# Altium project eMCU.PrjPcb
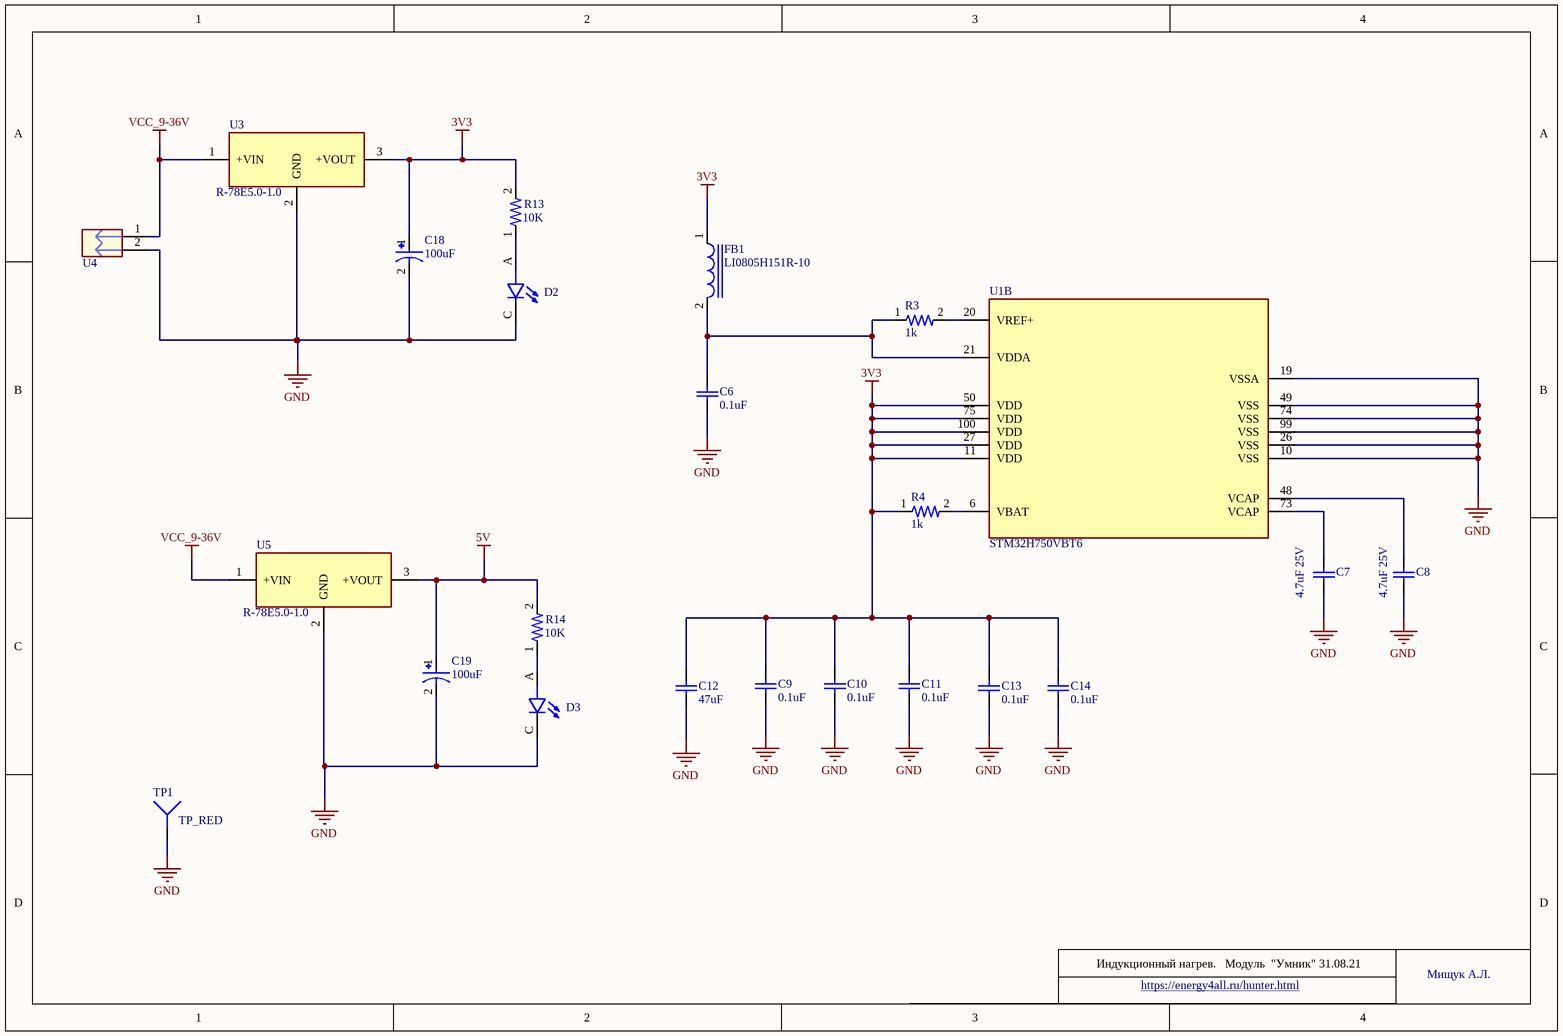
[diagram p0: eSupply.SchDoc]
6 sheets, 104 parts. Net scope: flat (ports and power ports of the same name join across sheets).
Board file: eMCU.PcbDoc
Sheets:
  eSupply.SchDoc
  eMCU.SchDoc
  eUSB.SchDoc
  eWiFi.SchDoc
  eConnect.SchDoc
  Can.SchDoc

## Sheet eSupply.SchDoc
size A4; SheetNumber: 1; SheetTotal: 7

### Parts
(Parts that share a designator on the sheet are numbered #1, #2 ... from top to bottom, then left to right.)
C6  0.1uF  [CAP_0603]
C7  4.7uF 25V  [CAP_0603]
C8  4.7uF 25V  [CAP_0603]
C9  0.1uF  [CAP_0603]
C10  0.1uF  [CAP_0603]
C11  0.1uF  [CAP_0603]
C12  47uF  [CAP_1210]
C13  0.1uF  [CAP_0603]
C14  0.1uF  [CAP_0603]
C18  100uF  [CAP_TYPE_D]
C19  100uF  [CAP_TYPE_D]
D2#1  led_0603  [led_0603]  (value not drawn)
D3  led_0603  [led_0603]  (value not drawn)
FB1  LI0805H151R-10  [LI0805H151R-10]
R3  1k  [RESC1608X50N]
R4  1k  [RESC1608X50N]
R13  10K  [RESC1608X50N]
R14  10K  [RESC1608X50N]
TP1  TP_RED  [TP_RED]
U1  STM32H750VBT6  [STM32H750VBT6]  (part B of 5)
U3  R-78E5.0-1.0  [R-78E5.0-1.0]
U4  DG129-5.0-02P  [DG129-5.0-02P]  (value not drawn)
U5  R-78E5.0-1.0  [R-78E5.0-1.0]

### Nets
3V3: C9.2 C10.2 C11.2 C12.2 C13.2 C14.2 C18.1 FB1.1 R4.1 R13.2 U1.11(VDD) U1.27(VDD) U1.50(VDD) U1.75(VDD) U1.100(VDD) U3.3(+VOUT)
5V: C19.1 R14.2 U5.3(+VOUT)
GND: C6.1 C7.1 C8.1 C9.1 C10.1 C11.1 C12.1 C13.1 C14.1 C18.2 C19.2 D2#1.C D3.C TP1.1 U1.10(VSS) U1.19(VSSA) U1.26(VSS) U1.49(VSS) U1.74(VSS) U1.99(VSS) U3.2(GND) U4.2 U5.2(GND)
VCC_9-36V: U3.1(+VIN) U4.1 U5.1(+VIN)
NetC6_2: C6.2 FB1.2 R3.1 U1.21(VDDA)
NetC7_2: C7.2 U1.73(VCAP)
NetC8_2: C8.2 U1.48(VCAP)
NetD2#1_A: D2#1.A R13.1
NetD3_A: D3.A R14.1
NetR3_2: R3.2 U1.20(VREF+)
NetR4_2: R4.2 U1.6(VBAT)

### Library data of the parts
C6-C11 C13 C14 = CAP_0603
C12 = CAP_1210
C18 C19 = CAP_TYPE_D: MP: 25TQC15MV
D2#1 D3 = led_0603: LED Indication - Discrete 3.1V 0603 _1608 Metric_; MP: LTW-C191TLA; MF: Lite-On
FB1 = LI0805H151R-10: 150 Ohms @ 100MHz 1 Power, Signal Line Ferrite Bead 0805 (2012 Metric) 800mA 150mOhm; MF: Laird-Signal Integrity
R3 R4 R13 R14 = RES_0603: 1% 0.1W; MP: 1-2176071-4
TP1 = TP_RED: RF EMI Absorbing Sheet - Polyurethane Foam 24.000 (609.60mm) X 24.000 (609.60mm) X 0.252 (6.40mm); MF: Aeroflex; MP: 5010
U1 = STM32H750VBT6: ARM Cortex-M7 STM32H7 Microcontroller IC 32-Bit 480MHz 128KB _128K x 8_ FLASH 100-LQFP _14x14_; MF: STMicroelectronics
U3 U5 = R-78E5.0-1.0: 1A DC/DC-Converter SIP3; MF: Recom Power
U4 = DG129-5.0-02P: DG129-5.0-02P-14-00A(H)

## Sheet eMCU.SchDoc
size A4; SheetNumber: 2; SheetTotal: 7
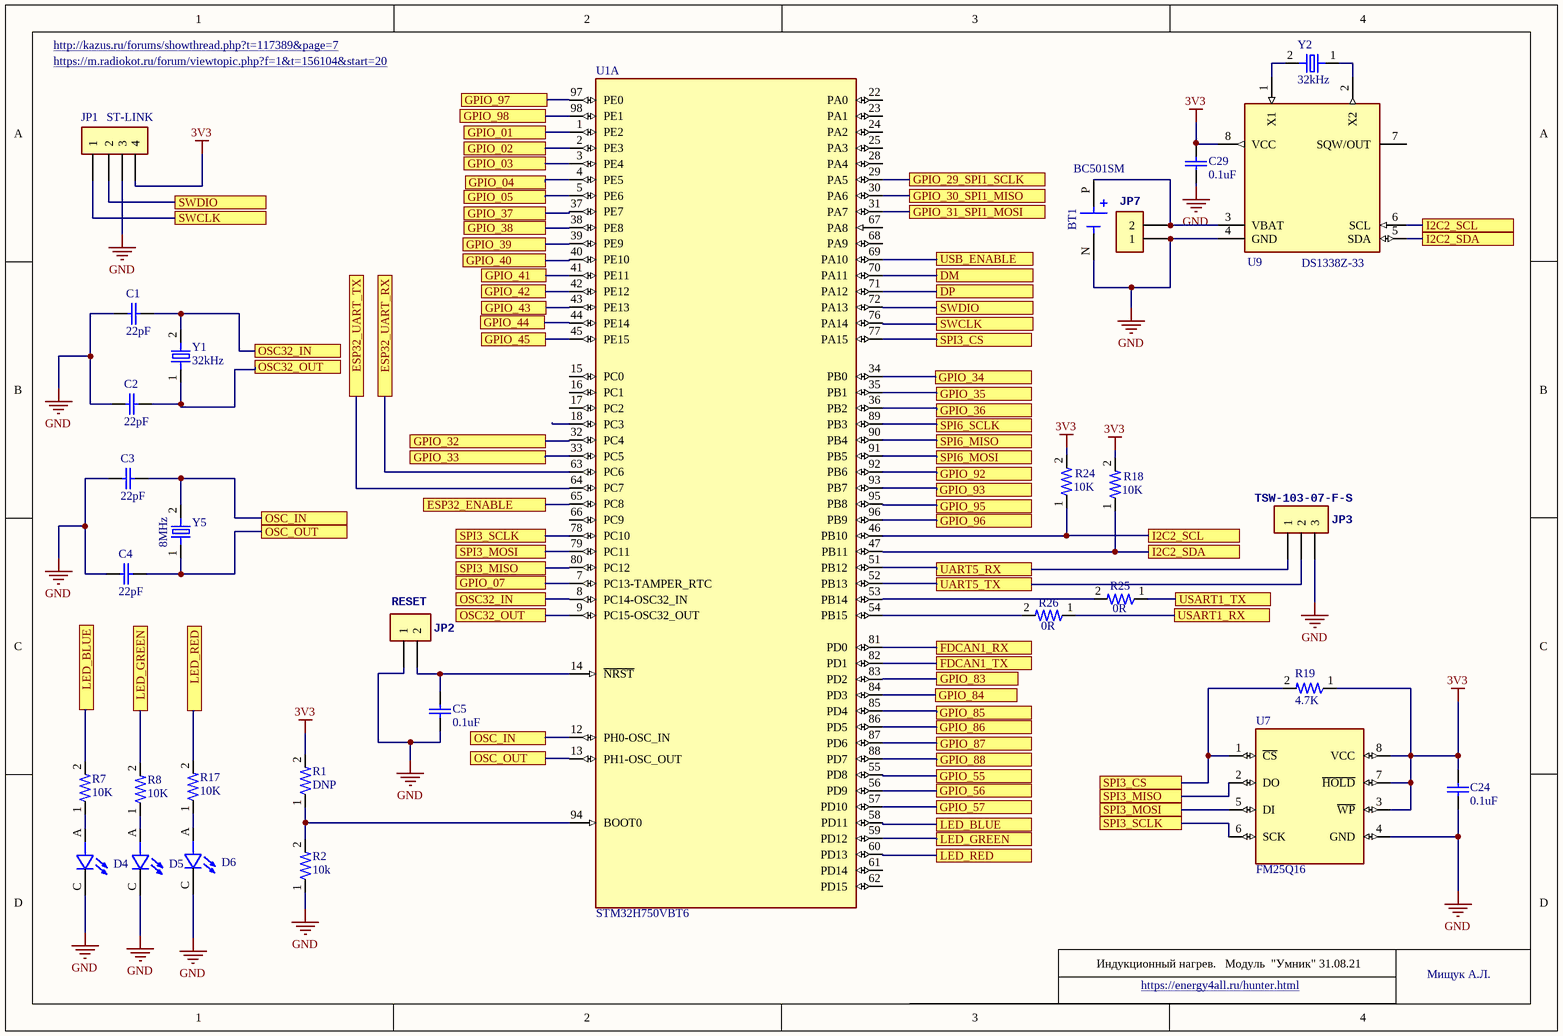
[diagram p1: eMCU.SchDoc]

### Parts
BT1  BC501SM  [BAT_BC501SM]
C1  22pF  [CAP_0603]
C2  22pF  [CAP_0603]
C3  22pF  [CAP_0603]
C4  22pF  [CAP_0603]
C5  0.1uF  [CAP_0603]
C24  0.1uF  [CAP_0603]
C29  0.1uF  [CAP_0603]
D4  led_0603  [led_0603]  (value not drawn)
D5  led_0603  [led_0603]  (value not drawn)
D6  led_0603  [led_0603]  (value not drawn)
JP1  ST-LINK  [TSW-104-07-F-S]
JP2  RESET  [TSW-102-07-F-S]
JP3  TSW-103-07-F-S  [TSW-103-07-F-S]
JP7  TSW-102-07-F-S  [TSW-102-07-F-S]  (value not drawn)
R1  DNP  [RESC1608X50N]
R2  10k  [RESC1608X50N]
R7  10K  [RESC1608X50N]
R8  10K  [RESC1608X50N]
R17  10K  [RESC1608X50N]
R18  10K  [RESC1608X50N]
R19  4.7K  [RESC1608X50N]
R24  10K  [RESC1608X50N]
R25  0R  [RESC1608X50N]
R26  0R  [RESC1608X50N]
U1  STM32H750VBT6  [STM32H750VBT6]  (part A of 5)
U7  FM25Q16  [FM25Q16]
U9  DS1338Z-33  [DS1338Z-33]
Y1  32kHz  [NX3215SA]
Y2  32kHz  [NX3215SA]
Y5  8MHz  [NX3225GD]

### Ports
DM, DP, ESP32_ENABLE, ESP32_UART_RX, ESP32_UART_TX, FDCAN1_RX, FDCAN1_TX, GPIO_01, GPIO_02, GPIO_03, GPIO_04, GPIO_05, GPIO_07, GPIO_29_SPI1_SCLK, GPIO_30_SPI1_MISO, GPIO_31_SPI1_MOSI, GPIO_32, GPIO_33, GPIO_34, GPIO_35, GPIO_36, GPIO_37, GPIO_38, GPIO_39, GPIO_40, GPIO_41, GPIO_42, GPIO_43, GPIO_44, GPIO_45, GPIO_55, GPIO_56, GPIO_57, GPIO_83, GPIO_84, GPIO_85, GPIO_86, GPIO_87, GPIO_88, GPIO_92, GPIO_93, GPIO_95, GPIO_96, GPIO_97, GPIO_98, I2C2_SCL, I2C2_SDA, LED_BLUE, LED_GREEN, LED_RED, OSC32_IN, OSC32_OUT, OSC_IN, OSC_OUT, SPI3_CS, SPI3_MISO, SPI3_MOSI, SPI3_SCLK, SPI6_MISO, SPI6_MOSI, SPI6_SCLK, SWCLK, SWDIO, UART5_RX, UART5_TX, USART1_RX, USART1_TX, USB_ENABLE

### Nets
3V3: C24.2 C29.2 JP1.4 R1.2 R18.2 R19.1 R24.2 U7.3(~{WP}) U7.7(~{HOLD}) U7.8(VCC) U9.8(VCC)
GND: BT1.N(NEG) C1.1 C2.1 C3.1 C4.1 C5.1 C24.1 C29.1 D4.C D5.C D6.C JP1.3 JP2.1 JP3.3 JP7.1 R2.1 U7.4(GND) U9.4(GND)
NetBT1_P: BT1.P(POS) JP7.2 U9.3(VBAT)
NetC1_2: C1.2 U1.8(PC14-OSC32_IN) Y1.2 ; port OSC32_IN
NetC2_2: C2.2 U1.9(PC15-OSC32_OUT) Y1.1 ; port OSC32_OUT
NetC3_2: C3.2 U1.12(PH0-OSC_IN) Y5.2 ; port OSC_IN
NetC4_2: C4.2 U1.13(PH1-OSC_OUT) Y5.1 ; port OSC_OUT
NetC5_2: C5.2 JP2.2 U1.14(~{NRST})
NetC21_2: U1.65(PC8) ; port ESP32_ENABLE
NetD4_A: D4.A R7.1
NetD5_A: D5.A R8.1
NetD6_A: D6.A R17.1
NetIDC1_3: U1.41(PE11) ; port GPIO_41
NetIDC1_4: U1.42(PE12) ; port GPIO_42
NetIDC1_5: U1.43(PE13) ; port GPIO_43
NetIDC1_6: U1.44(PE14) ; port GPIO_44
NetIDC1_7: U1.45(PE15) ; port GPIO_45
NetIDC1_8: U1.57(PD10) ; port GPIO_57
NetIDC1_9: U1.56(PD9) ; port GPIO_56
NetIDC1_10: U1.55(PD8) ; port GPIO_55
NetIDC2_4: U1.83(PD2) ; port GPIO_83
NetIDC2_5: U1.84(PD3) ; port GPIO_84
NetIDC2_6: U1.85(PD4) ; port GPIO_85
NetIDC2_7: U1.86(PD5) ; port GPIO_86
NetIDC2_8: U1.87(PD6) ; port GPIO_87
NetIDC2_9: U1.88(PD7) ; port GPIO_88
NetIDC2_10: U1.89(PB3) ; port SPI6_SCLK
NetIDC2_11: U1.90(PB4) ; port SPI6_MISO
NetIDC2_12: U1.91(PB5) ; port SPI6_MOSI
NetIDC2_13: U1.92(PB6) ; port GPIO_92
NetIDC2_14: U1.93(PB7) ; port GPIO_93
NetIDC2_15: U1.95(PB8) ; port GPIO_95
NetIDC2_16: U1.96(PB9) ; port GPIO_96
NetIDC2_17: U1.97(PE0) ; port GPIO_97
NetIDC2_18: U1.98(PE1) ; port GPIO_98
NetIDC2_19: U1.7(PC13-TAMPER_RTC) ; port GPIO_07
NetIDC2_20: U1.1(PE2) ; port GPIO_01
NetIDC2_21: U1.2(PE3) ; port GPIO_02
NetIDC2_22: U1.3(PE4) ; port GPIO_03
NetIDC2_23: U1.4(PE5) ; port GPIO_04
NetIDC2_24: U1.5(PE6) ; port GPIO_05
NetIDC3_3: U1.29(PA5) ; port GPIO_29_SPI1_SCLK
NetIDC3_4: U1.30(PA6) ; port GPIO_30_SPI1_MISO
NetIDC3_5: U1.31(PA7) ; port GPIO_31_SPI1_MOSI
NetIDC3_6: U1.32(PC4) ; port GPIO_32
NetIDC3_7: U1.33(PC5) ; port GPIO_33
NetIDC3_8: U1.34(PB0) ; port GPIO_34
NetIDC3_9: U1.35(PB1) ; port GPIO_35
NetIDC3_10: U1.36(PB2) ; port GPIO_36
NetIDC3_11: U1.37(PE7) ; port GPIO_37
NetIDC3_12: U1.38(PE8) ; port GPIO_38
NetIDC3_13: U1.39(PE9) ; port GPIO_39
NetIDC3_14: U1.40(PE10) ; port GPIO_40
NetJ1_2: U1.70(PA11) ; port DM
NetJ1_3: U1.71(PA12) ; port DP
NetJ4_3: U1.64(PC7) ; port ESP32_UART_TX
NetJ4_4: U1.63(PC6) ; port ESP32_UART_RX
NetJP1_1: JP1.1 U1.76(PA14) ; port SWCLK
NetJP1_2: JP1.2 U1.72(PA13) ; port SWDIO
NetJP3_1: JP3.1 U1.51(PB12) ; port UART5_RX
NetJP3_2: JP3.2 U1.52(PB13) ; port UART5_TX
NetJP6_2: R26.1 ; port USART1_RX
NetJP6_3: R25.1 ; port USART1_TX
NetR1_1: R1.1 R2.2 U1.94(BOOT0)
NetR7_2: R7.2 U1.58(PD11) ; port LED_BLUE
NetR8_2: R8.2 U1.59(PD12) ; port LED_GREEN
NetR10_2: U1.69(PA10) ; port USB_ENABLE
NetR17_2: R17.2 U1.60(PD13) ; port LED_RED
NetR18_1: R18.1 U1.47(PB11) U9.5(SDA) ; port I2C2_SDA
NetR19_2: R19.2 U1.77(PA15) U7.1(~{CS}) ; port SPI3_CS
NetR24_1: R24.1 U1.46(PB10) U9.6(SCL) ; port I2C2_SCL
NetR25_2: R25.2 U1.53(PB14)
NetR26_2: R26.2 U1.54(PB15)
NetU1_78: U1.78(PC10) U7.6(SCK) ; port SPI3_SCLK
NetU1_79: U1.79(PC11) U7.5(DI) ; port SPI3_MOSI
NetU1_80: U1.80(PC12) U7.2(DO) ; port SPI3_MISO
NetU1_81: U1.81(PD0) ; port FDCAN1_RX
NetU1_82: U1.82(PD1) ; port FDCAN1_TX
NetU9_1: U9.1(X1) Y2.2
NetU9_2: U9.2(X2) Y2.1

Not connected (* = marked no-connect by the designer): U1 15(PC0) 16(PC1) 17(PC2) 18(PC3) 22(PA0) 23(PA1) 24(PA2) 25(PA3) 28(PA4) 61(PD14) 62(PD15) 66(PC9) 67(PA8) 68(PA9); U9 7(SQW/OUT)

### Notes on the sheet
- http://kazus.ru/forums/showthread.php?t=117389&page=7
- https://m.radiokot.ru/forum/viewtopic.php?f=1&t=156104&start=20

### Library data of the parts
BT1 = BAT_BC501SM: BATTERY HOLDER COIN 12MM SMD; MF: MPD
C1-C5 C24 C29 = CAP_0603
D4-D6 = led_0603: as D2#1 on sheet eSupply
JP1 = TSW-104-07-F-S: Connector Header Through Hole 4 position 0.100 (2.54mm); MP: TSW-104-24-G-S; MF: Samtec
JP2 = TSW-102-07-F-S
R1 R2 R7 R8 R17-R19 R24-R26 = RES_0603: 1% 0.1W; MP: 1-2176071-4
U1 = STM32H750VBT6: as U1 on sheet eSupply
U7 = FM25Q16: Serial Flash Memory with 4KB Sectors SPI SOIC-8; MP: FM25W256-G; MF: Cypress Semiconductor
U9 = DS1338Z-33: Real Time Clock (RTC) IC Clock/Calendar 56B IÂ²C, 2-Wire Serial 8-SOIC (0.154, 3.90mm Width); MP: DS1338Z-33+; MF: Maxim Integrated
Y1 Y2 = NX3215SA-32.768K-STD-MUA-8: 32.768 kHz Â±20ppm Crystal 12.5pF 70 kOhms 2-SMD, No Lead; MF: NDK America,
Y5 = NX3225GD: 8MHz Â±20ppm Crystal 18pF 140 Ohms 2-SMD, No Lead; MP: ABM3-8.000MHZ-D2Y-T; MF: Abracon

## Sheet eUSB.SchDoc
size A4; SheetNumber: 3; SheetTotal: 7
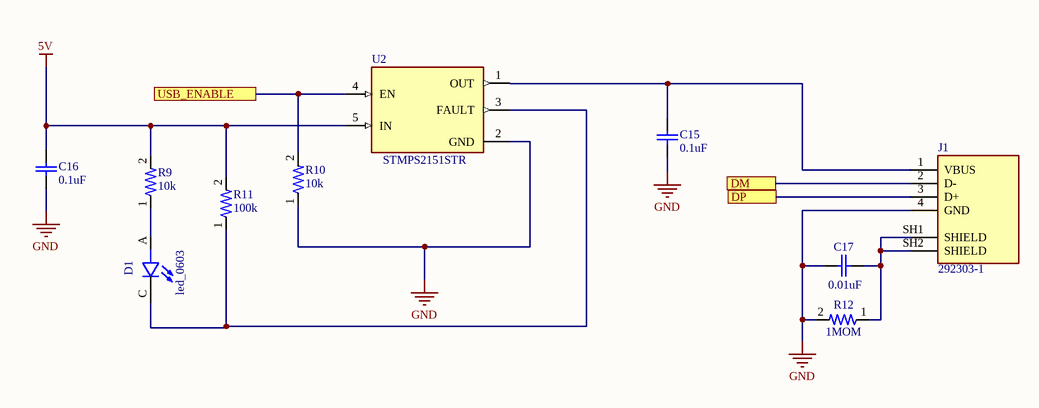
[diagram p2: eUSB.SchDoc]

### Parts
C15  0.1uF  [CAP_0603]
C16  0.1uF  [CAP_0603]
C17  0.01uF  [CAP_0603]
D1  led_0603  [led_0603]
J1  292303-1  [TE_292303-1]
R9  10k  [RESC1608X50N]
R10  10k  [RESC1608X50N]
R11  100k  [RESC1608X50N]
R12  1MOM  [RESC1608X50N]
U2  STMPS2151STR  [STMPS2151STR]

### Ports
DM, DP, USB_ENABLE

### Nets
5V: C16.1 R9.2 R11.2 U2.5(IN)
GND: C15.2 C16.2 C17.1 J1.4(GND) R10.1 R12.2 U2.2(GND)
NetC15_1: C15.1 J1.1(VBUS) U2.1(OUT)
NetC17_2: C17.2 J1.SH1(SHIELD) J1.SH2(SHIELD) R12.1
NetD1_A: D1.A R9.1
NetD1_C: D1.C R11.1 U2.3(FAULT)
NetJ1_2: J1.2(D-) ; port DM
NetJ1_3: J1.3(D+) ; port DP
NetR10_2: R10.2 U2.4(EN) ; port USB_ENABLE

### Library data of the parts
C15-C17 = CAP_0603
D1 = led_0603: as D2#1 on sheet eSupply
J1 = 292303-1: Conn; Data; USB; Recept; 2.0; 4 Pos; 1 Port; Rt Angle; A Ser; Tin over Copper; Number_of_Positions: 4; Centerline_Pitch: 2 mm[.078 in]; MF: TE Connectivity; Product_Type: Connector
R9-R12 = RES_0603: 1% 0.1W; MP: 1-2176071-4
U2 = STMPS2141STR: Power Switch/Driver 1:1 N-Channel 500mA SOT-23-5; MF: STMicroelectronics

## Sheet eWiFi.SchDoc
size A4; SheetNumber: 4; SheetTotal: 7
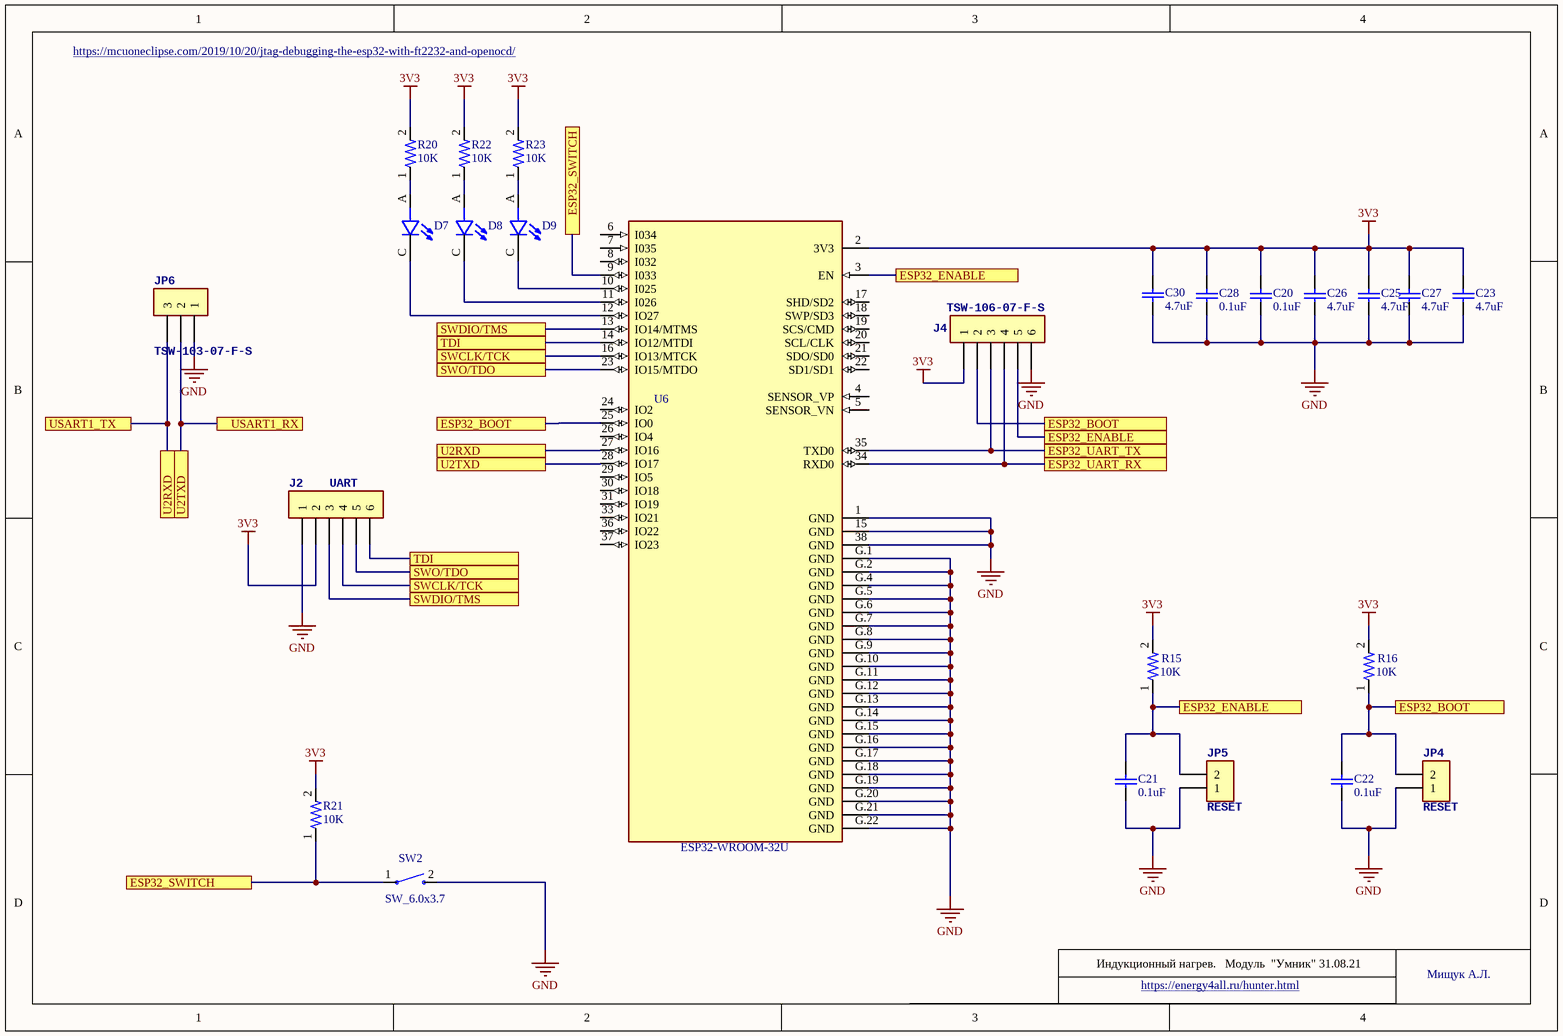
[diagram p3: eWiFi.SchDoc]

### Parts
C20  0.1uF  [CAP_0603]
C21  0.1uF  [CAP_0603]
C22  0.1uF  [CAP_0603]
C23  4.7uF  [CAP_0603]
C25  4.7uF  [CAP_0603]
C26  4.7uF  [CAP_0603]
C27  4.7uF  [CAP_0603]
C28  0.1uF  [CAP_0603]
C30  4.7uF  [CAP_0603]
D7  led_0603  [led_0603]  (value not drawn)
D8  led_0603  [led_0603]  (value not drawn)
D9  led_0603  [led_0603]  (value not drawn)
J2  UART  [TSW-106-07-F-S]
J4  TSW-106-07-F-S  [TSW-106-07-F-S]
JP4  RESET  [TSW-102-07-F-S]
JP5  RESET  [TSW-102-07-F-S]
JP6  TSW-103-07-F-S  [TSW-103-07-F-S]
R15  10K  [RESC1608X50N]
R16  10K  [RESC1608X50N]
R20  10K  [RESC1608X50N]
R21  10K  [RESC1608X50N]
R22  10K  [RESC1608X50N]
R23  10K  [RESC1608X50N]
SW2  SW_6.0x3.7  [SW_6.0x3.7]
U6  ESP32-WROOM-32U  [ESP32-WROOM-32U]

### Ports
ESP32_BOOT, ESP32_ENABLE, ESP32_SWITCH, ESP32_UART_RX, ESP32_UART_TX, SWCLK/TCK, SWDIO/TMS, SWO/TDO, TDI, U2RXD, U2TXD, USART1_RX, USART1_TX

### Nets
3V3: C20.2 C23.2 C25.2 C26.2 C27.2 C28.2 C30.1 J2.2 J4.1 R15.2 R16.2 R20.2 R21.2 R22.2 R23.2 U6.2(3V3)
GND: C20.1 C21.1 C22.1 C23.1 C25.1 C26.1 C27.1 C28.1 C30.2 J2.1 J4.6 JP4.1 JP5.1 JP6.1 SW2.2 U6.1(GND) U6.15(GND) U6.38(GND) U6.G.1(GND) U6.G.2(GND) U6.G.4(GND) U6.G.5(GND) U6.G.6(GND) U6.G.7(GND) U6.G.8(GND) U6.G.9(GND) U6.G.10(GND) U6.G.11(GND) U6.G.12(GND) U6.G.13(GND) U6.G.14(GND) U6.G.15(GND) U6.G.16(GND) U6.G.17(GND) U6.G.18(GND) U6.G.19(GND) U6.G.20(GND) U6.G.21(GND) U6.G.22(GND)
NetC21_2: C21.2 J4.5 JP5.2 R15.1 U6.3(EN) ; port ESP32_ENABLE
NetC22_2: C22.2 J4.2 JP4.2 R16.1 U6.25(IO0) ; port ESP32_BOOT
NetD7_A: D7.A R20.1
NetD7_C: D7.C U6.12(IO27)
NetD8_A: D8.A R22.1
NetD8_C: D8.C U6.11(I026)
NetD9_A: D9.A R23.1
NetD9_C: D9.C U6.10(I025)
NetJ2_3: J2.3 U6.13(IO14/MTMS) ; port SWDIO/TMS
NetJ2_4: J2.4 U6.16(IO13/MTCK) ; port SWCLK/TCK
NetJ2_5: J2.5 U6.23(IO15/MTDO) ; port SWO/TDO
NetJ2_6: J2.6 U6.14(IO12/MTDI) ; port TDI
NetJ4_3: J4.3 U6.35(TXD0) ; port ESP32_UART_TX
NetJ4_4: J4.4 U6.34(RXD0) ; port ESP32_UART_RX
NetJP6_2: JP6.2 U6.28(IO17) ; port U2TXD, port USART1_RX
NetJP6_3: JP6.3 U6.27(IO16) ; port U2RXD, port USART1_TX
NetR21_1: R21.1 SW2.1 U6.9(I033) ; port ESP32_SWITCH

Not connected (* = marked no-connect by the designer): U6 4(SENSOR_VP) 5(SENSOR_VN) 6(I034) 7(I035) 8(I032) 17(SHD/SD2) 18(SWP/SD3) 19(SCS/CMD) 20(SCL/CLK) 21(SDO/SD0) 22(SD1/SD1) 24(IO2) 26(IO4) 29(IO5) 30(IO18) 31(IO19) 33(IO21) 36(IO22) 37(IO23)

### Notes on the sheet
- https://mcuoneclipse.com/2019/10/20/jtag-debugging-the-esp32-with-ft2232-and-openocd/

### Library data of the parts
C20-C23 C25-C28 C30 = CAP_0603
D7-D9 = led_0603: as D2#1 on sheet eSupply
J2 = TSW-106-07-F-S
JP4 JP5 = TSW-102-07-F-S
R15 R16 R20-R23 = RES_0603: 1% 0.1W; MP: 1-2176071-4
SW2 = SW_6.0x3.7: Switch Tactile OFF (ON) SPST Rectangular Button Gull Wing 0.05A 12VDC SMD Loose Piece; MP: 1437566-3
U6 = ESP32-WROOM-32U: Bluetooth, WiFi 802.11b/g/n, Bluetooth v4.2 +EDR, Class 1, 2 and 3 Transceiver Module 2.4GHz ~ 2.5GHz Antenna Not Included, U.FL Surface Mount; MF: Espressif Systems

## Sheet eConnect.SchDoc
size A4; SheetNumber: 5; SheetTotal: 7
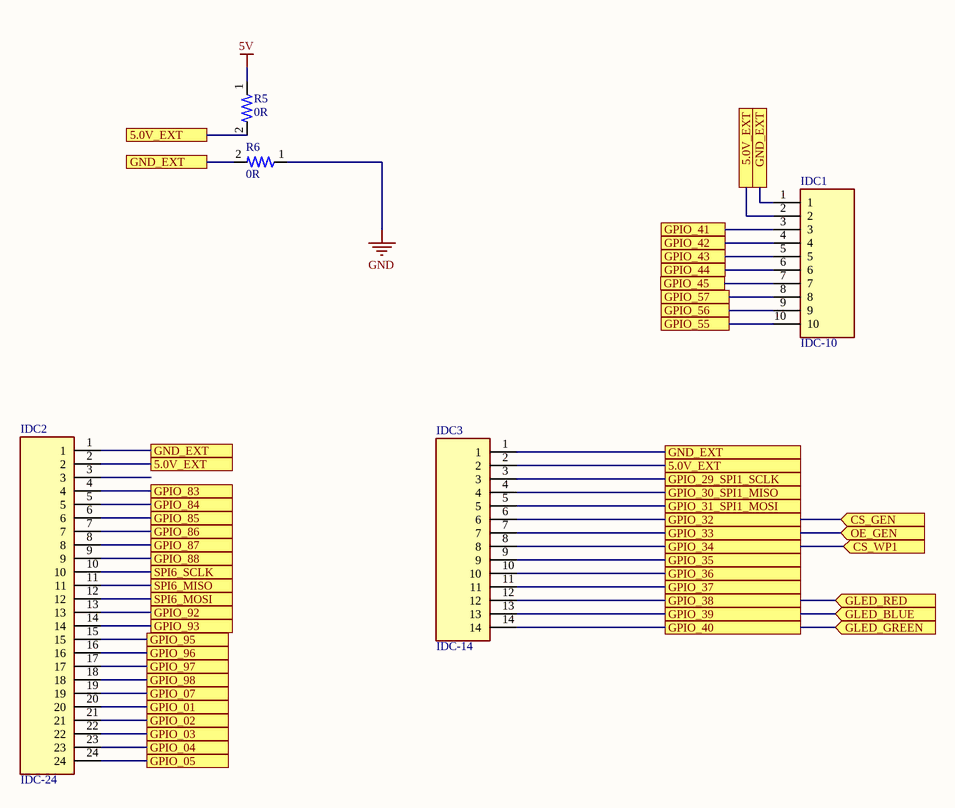
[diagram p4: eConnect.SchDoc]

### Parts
IDC1  IDC-10  [IDC-10]
IDC2  IDC-24  [IDC-24]
IDC3  IDC-14  [IDC-14]
R5  0R  [RESC1608X50N]
R6  0R  [RESC1608X50N]

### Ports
5.0V_EXT, CS_GEN (in), CS_WP1 (in), GLED_BLUE (in), GLED_GREEN (in), GLED_RED (in), GND_EXT, GPIO_01, GPIO_02, GPIO_03, GPIO_04, GPIO_05, GPIO_07, GPIO_29_SPI1_SCLK, GPIO_30_SPI1_MISO, GPIO_31_SPI1_MOSI, GPIO_32, GPIO_33, GPIO_34, GPIO_35, GPIO_36, GPIO_37, GPIO_38, GPIO_39, GPIO_40, GPIO_41, GPIO_42, GPIO_43, GPIO_44, GPIO_45, GPIO_55, GPIO_56, GPIO_57, GPIO_83, GPIO_84, GPIO_85, GPIO_86, GPIO_87, GPIO_88, GPIO_92, GPIO_93, GPIO_95, GPIO_96, GPIO_97, GPIO_98, OE_GEN (in), SPI6_MISO, SPI6_MOSI, SPI6_SCLK

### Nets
5V: R5.1
GND: R6.1
NetIDC1_1: IDC1.1 IDC2.1 IDC3.1 R6.2 ; port GND_EXT
NetIDC1_2: IDC1.2 IDC2.2 IDC3.2 R5.2 ; port 5.0V_EXT
NetIDC1_3: IDC1.3 ; port GPIO_41
NetIDC1_4: IDC1.4 ; port GPIO_42
NetIDC1_5: IDC1.5 ; port GPIO_43
NetIDC1_6: IDC1.6 ; port GPIO_44
NetIDC1_7: IDC1.7 ; port GPIO_45
NetIDC1_8: IDC1.8 ; port GPIO_57
NetIDC1_9: IDC1.9 ; port GPIO_56
NetIDC1_10: IDC1.10 ; port GPIO_55
NetIDC2_4: IDC2.4 ; port GPIO_83
NetIDC2_5: IDC2.5 ; port GPIO_84
NetIDC2_6: IDC2.6 ; port GPIO_85
NetIDC2_7: IDC2.7 ; port GPIO_86
NetIDC2_8: IDC2.8 ; port GPIO_87
NetIDC2_9: IDC2.9 ; port GPIO_88
NetIDC2_10: IDC2.10 ; port SPI6_SCLK
NetIDC2_11: IDC2.11 ; port SPI6_MISO
NetIDC2_12: IDC2.12 ; port SPI6_MOSI
NetIDC2_13: IDC2.13 ; port GPIO_92
NetIDC2_14: IDC2.14 ; port GPIO_93
NetIDC2_15: IDC2.15 ; port GPIO_95
NetIDC2_16: IDC2.16 ; port GPIO_96
NetIDC2_17: IDC2.17 ; port GPIO_97
NetIDC2_18: IDC2.18 ; port GPIO_98
NetIDC2_19: IDC2.19 ; port GPIO_07
NetIDC2_20: IDC2.20 ; port GPIO_01
NetIDC2_21: IDC2.21 ; port GPIO_02
NetIDC2_22: IDC2.22 ; port GPIO_03
NetIDC2_23: IDC2.23 ; port GPIO_04
NetIDC2_24: IDC2.24 ; port GPIO_05
NetIDC3_3: IDC3.3 ; port GPIO_29_SPI1_SCLK
NetIDC3_4: IDC3.4 ; port GPIO_30_SPI1_MISO
NetIDC3_5: IDC3.5 ; port GPIO_31_SPI1_MOSI
NetIDC3_6: IDC3.6 ; port GPIO_32, port CS_GEN
NetIDC3_7: IDC3.7 ; port GPIO_33, port OE_GEN
NetIDC3_8: IDC3.8 ; port GPIO_34, port CS_WP1
NetIDC3_9: IDC3.9 ; port GPIO_35
NetIDC3_10: IDC3.10 ; port GPIO_36
NetIDC3_11: IDC3.11 ; port GPIO_37
NetIDC3_12: IDC3.12 ; port GPIO_38, port GLED_RED
NetIDC3_13: IDC3.13 ; port GPIO_39, port GLED_BLUE
NetIDC3_14: IDC3.14 ; port GPIO_40, port GLED_GREEN

Not connected (* = marked no-connect by the designer): IDC2 3

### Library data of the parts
IDC1 = IDC-10: Header, Pin, Idc, Amp-Latch, 10 Pos, Low Profile, Pcb, Vertical, Blue; MF: TE Connectivity; MP: 2-1761603-3; Centerline_Pitch: 2.54 mm[.1 in]; Product_Type: Connector; Number_of_Positions: 10
IDC2 = IDC-24: IDC LOW PRO HDR 24P VERT BLUE; MF: TE Connectivity; MP: 2-1761603-8
IDC3 = IDC-14: HEADER, PIN, AMP-LATCH, 14 POS, 2.54 X 2.54, VERTICAL, LOW PROFILE, PCB; MP: 5104338-2; Product_Type: Connector; Centerline_Pitch: 2.54 mm[.1 in]; MF: TE Connectivity; Number_of_Positions: 14
R5 R6 = RES_0603: 1% 0.1W; MP: 1-2176071-4

## Sheet Can.SchDoc
size A4; SheetNumber: 7; SheetTotal: 7
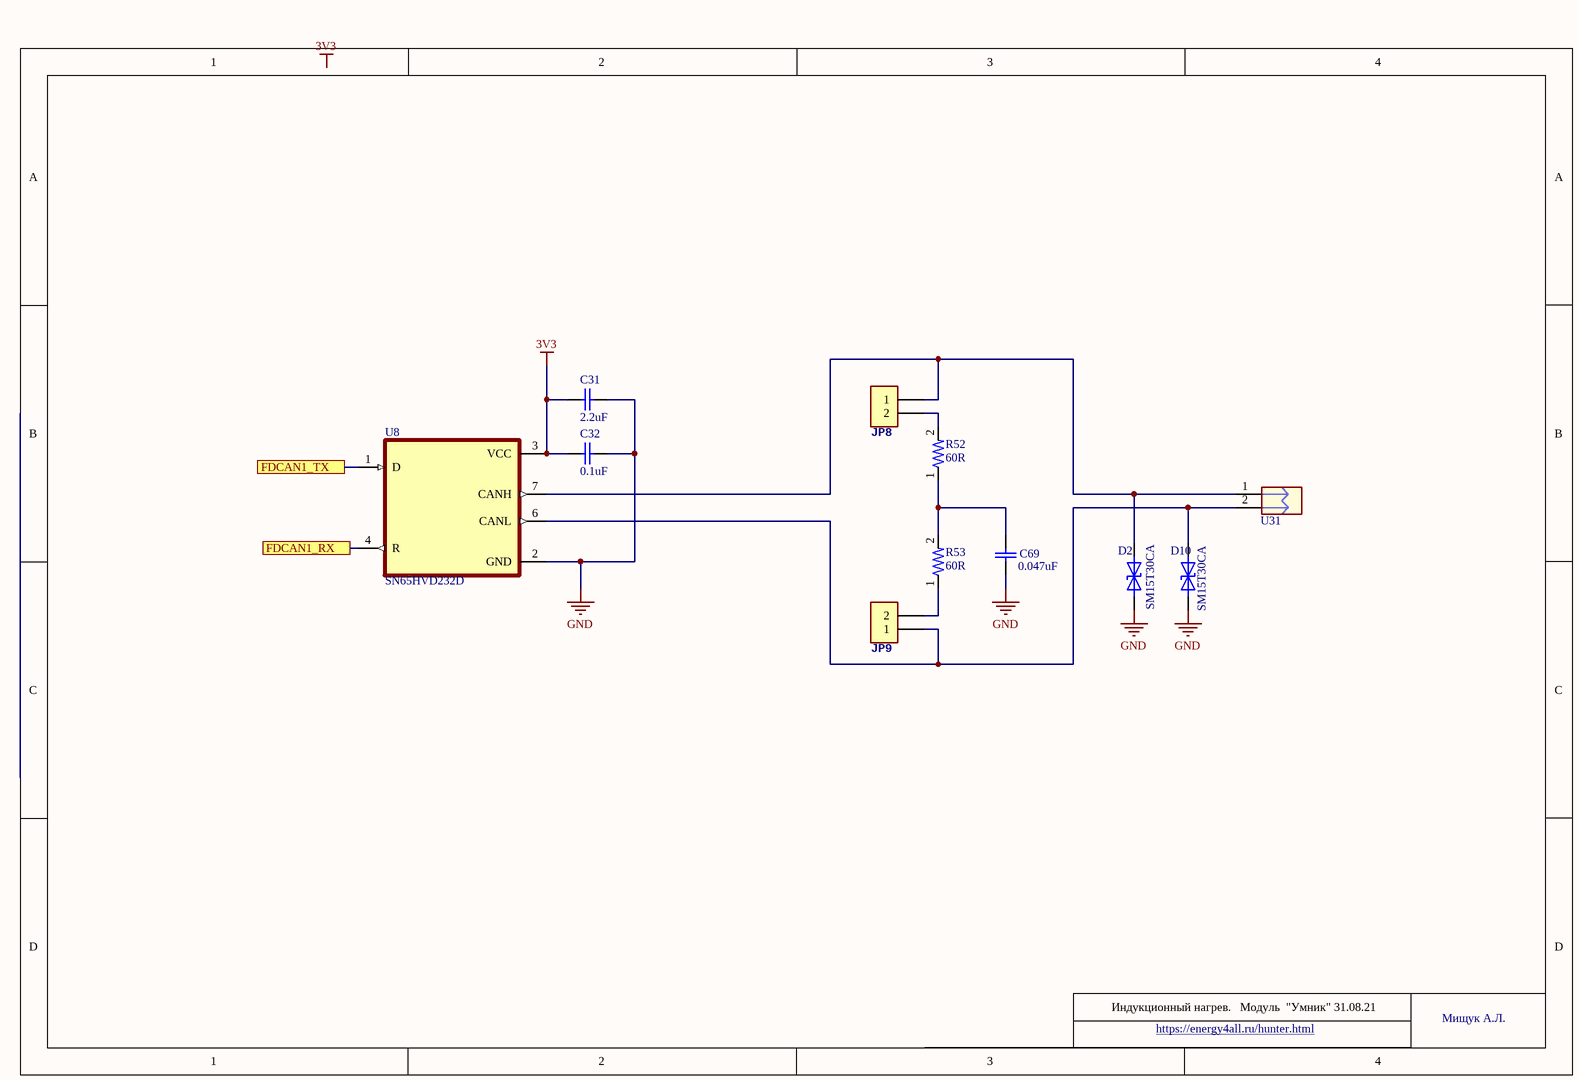
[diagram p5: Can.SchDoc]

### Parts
(Parts that share a designator on the sheet are numbered #1, #2 ... from top to bottom, then left to right.)
C31  2.2uF  [CAP_0603]
C32  0.1uF  [CAP_0603]
C69  0.047uF  [CAP_0603]
D2#2  SM15T30CA  [SM15T30CA]
D10  SM15T30CA  [SM15T30CA]
JP8  TSW-102-07-F-S  [TSW-102-07-F-S]  (value not drawn)
JP9  TSW-102-07-F-S  [TSW-102-07-F-S]  (value not drawn)
R52  60R  [RES_1206]
R53  60R  [RES_1206]
U8  SN65HVD232D  [SN65HVD232D]
U31  DG129-5.0-02P  [DG129-5.0-02P]  (value not drawn)

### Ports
FDCAN1_RX, FDCAN1_TX

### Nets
3V3: C31.2 C32.2 U8.3(VCC)
GND: C31.1 C32.1 C69.1 D2#2.1 D10.1 U8.2(GND)
NetC69_2: C69.2 R52.1 R53.2
NetD2#2_2: D2#2.2 JP8.1 U8.7(CANH) U31.1
NetD10_2: D10.2 JP9.1 U8.6(CANL) U31.2
NetJP8_2: JP8.2 R52.2
NetJP9_2: JP9.2 R53.1
NetU1_81: U8.4(R) ; port FDCAN1_RX
NetU1_82: U8.1(D) ; port FDCAN1_TX

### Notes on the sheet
- Labels drawn without touching a wire or pin: 3V3

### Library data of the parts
C31 C32 C69 = CAP_0603
D2#2 D10 = SM15T30CA: 1500 W, 25.6 V TVS; MF: ON Semiconductor; MP: SMCJ70CA
R52 R53 = RES_1206: 1% 1/4W; MP: 1-2176071-4
U8 = SN65HVD232D: 3.3 V CAN Transceiver; MF: Texas Instruments
U31 = DG129-5.0-02P: DG129-5.0-02P-14-00A(H)

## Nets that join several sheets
3V3: eSupply (16 pins), eMCU (11 pins), eWiFi (16 pins), Can (C31.2 C32.2 U8.3)
5V: eSupply (C19.1 R14.2 U5.3), eUSB (C16.1 R9.2 R11.2 U2.5), eConnect (R5.1)
GND: eSupply (23 pins), eMCU (18 pins), eUSB (7 pins), eWiFi (39 pins), eConnect (R6.1), Can (6 pins)
NetC21_2: eMCU (U1.65), eWiFi (5 pins)
NetIDC1_3: eMCU (U1.41), eConnect (IDC1.3)
NetIDC1_4: eMCU (U1.42), eConnect (IDC1.4)
NetIDC1_5: eMCU (U1.43), eConnect (IDC1.5)
NetIDC1_6: eMCU (U1.44), eConnect (IDC1.6)
NetIDC1_7: eMCU (U1.45), eConnect (IDC1.7)
NetIDC1_8: eMCU (U1.57), eConnect (IDC1.8)
NetIDC1_9: eMCU (U1.56), eConnect (IDC1.9)
NetIDC1_10: eMCU (U1.55), eConnect (IDC1.10)
NetIDC2_4: eMCU (U1.83), eConnect (IDC2.4)
NetIDC2_5: eMCU (U1.84), eConnect (IDC2.5)
NetIDC2_6: eMCU (U1.85), eConnect (IDC2.6)
NetIDC2_7: eMCU (U1.86), eConnect (IDC2.7)
NetIDC2_8: eMCU (U1.87), eConnect (IDC2.8)
NetIDC2_9: eMCU (U1.88), eConnect (IDC2.9)
NetIDC2_10: eMCU (U1.89), eConnect (IDC2.10)
NetIDC2_11: eMCU (U1.90), eConnect (IDC2.11)
NetIDC2_12: eMCU (U1.91), eConnect (IDC2.12)
NetIDC2_13: eMCU (U1.92), eConnect (IDC2.13)
NetIDC2_14: eMCU (U1.93), eConnect (IDC2.14)
NetIDC2_15: eMCU (U1.95), eConnect (IDC2.15)
NetIDC2_16: eMCU (U1.96), eConnect (IDC2.16)
NetIDC2_17: eMCU (U1.97), eConnect (IDC2.17)
NetIDC2_18: eMCU (U1.98), eConnect (IDC2.18)
NetIDC2_19: eMCU (U1.7), eConnect (IDC2.19)
NetIDC2_20: eMCU (U1.1), eConnect (IDC2.20)
NetIDC2_21: eMCU (U1.2), eConnect (IDC2.21)
NetIDC2_22: eMCU (U1.3), eConnect (IDC2.22)
NetIDC2_23: eMCU (U1.4), eConnect (IDC2.23)
NetIDC2_24: eMCU (U1.5), eConnect (IDC2.24)
NetIDC3_3: eMCU (U1.29), eConnect (IDC3.3)
NetIDC3_4: eMCU (U1.30), eConnect (IDC3.4)
NetIDC3_5: eMCU (U1.31), eConnect (IDC3.5)
NetIDC3_6: eMCU (U1.32), eConnect (IDC3.6)
NetIDC3_7: eMCU (U1.33), eConnect (IDC3.7)
NetIDC3_8: eMCU (U1.34), eConnect (IDC3.8)
NetIDC3_9: eMCU (U1.35), eConnect (IDC3.9)
NetIDC3_10: eMCU (U1.36), eConnect (IDC3.10)
NetIDC3_11: eMCU (U1.37), eConnect (IDC3.11)
NetIDC3_12: eMCU (U1.38), eConnect (IDC3.12)
NetIDC3_13: eMCU (U1.39), eConnect (IDC3.13)
NetIDC3_14: eMCU (U1.40), eConnect (IDC3.14)
NetJ1_2: eMCU (U1.70), eUSB (J1.2)
NetJ1_3: eMCU (U1.71), eUSB (J1.3)
NetJ4_3: eMCU (U1.64), eWiFi (J4.3 U6.35)
NetJ4_4: eMCU (U1.63), eWiFi (J4.4 U6.34)
NetJP6_2: eMCU (R26.1), eWiFi (JP6.2 U6.28)
NetJP6_3: eMCU (R25.1), eWiFi (JP6.3 U6.27)
NetR10_2: eMCU (U1.69), eUSB (R10.2 U2.4)
NetU1_81: eMCU (U1.81), Can (U8.4)
NetU1_82: eMCU (U1.82), Can (U8.1)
